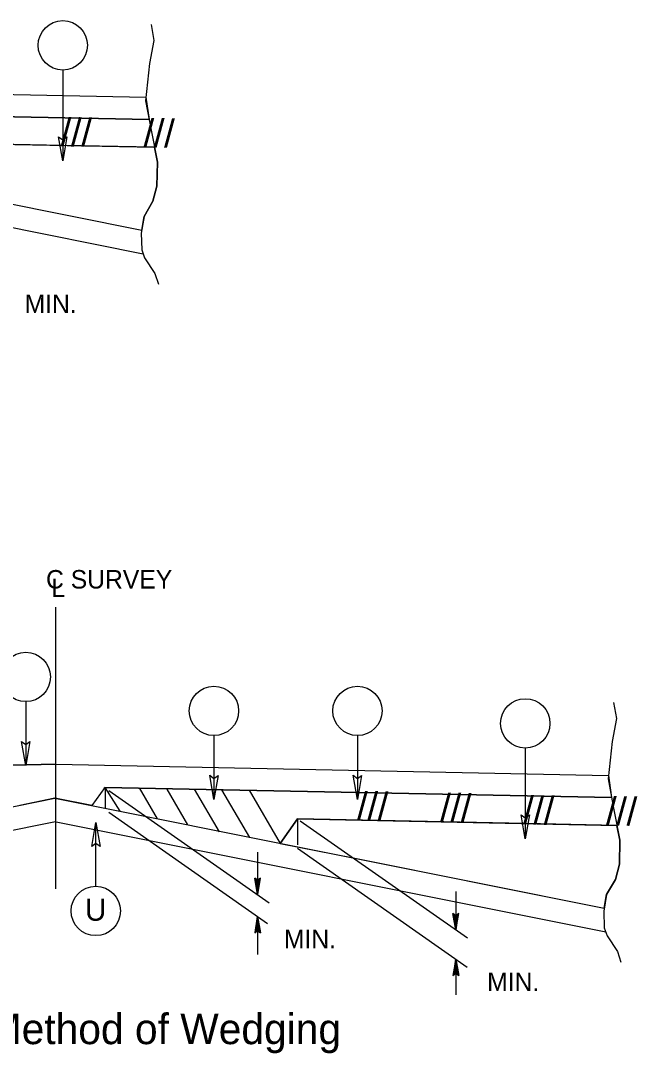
# Model space of a CAD drawing. Extents: x 1818040 to 1825768, y 638918 to 648046.
# Drawn here: x 1824618 to 1824981, y 640342 to 640948 of the extents above; entities that cross this region are included whole.
import ezdxf

# ---------------------------------------------------------------- set-up
doc = ezdxf.new("R2010")
doc.units = 0
for name, color, linetype in [('Typical Detail Wedge2 CELL', 7, 'Continuous'), ('Typical ID Circle CELL', 7, 'Continuous'), ('Typical Terminator CELL', 7, 'Continuous'), ('Typical Text Centerline CELL', 7, 'Continuous'), ('Typical Text General CELL', 7, 'Continuous'), ('Typical Text ID Circle CELL', 7, 'Continuous')]:
    doc.layers.add(name, color=color, linetype=linetype)

msp = doc.modelspace()

# ---------------------------------------------------------------- linework, layer by layer
at = {"layer": 'Typical Detail Wedge2 CELL'}
for p, q in [((1824367.22, 640909.96), (1824691.9, 640903.48)), ((1824367.25, 640909.96), (1824691.9, 640903.48)), ((1824691.9, 640903.48), (1824693.76, 640890.43)), ((1824395.95, 640896.39), (1824693.76, 640890.43)), ((1824693.76, 640890.43), (1824395.95, 640896.39)), ((1824366.74, 640890), (1824689.47, 640825.45)), ((1824509.25, 640877.84), (1824696.91, 640874.08)), ((1824643.09, 640875.16), (1824509.25, 640877.84)), ((1824367.35, 640876.11), (1824690.31, 640811.51)), ((1824696.91, 640874.08), (1824643.09, 640875.16)), ((1824541.94, 640854.95), (1824689.47, 640825.45)), ((1824638.97, 640438.55), (1824638.97, 640603.98)), ((1824638.97, 640438.55), (1824638.97, 640551.53)), ((1824638.96, 640511.63), (1824314.3, 640505.15)), ((1824314.3, 640505.15), (1824638.96, 640511.63)), ((1824638.96, 640511.63), (1824963.65, 640505.15)), ((1824639, 640511.63), (1824963.65, 640505.15)), ((1824963.65, 640505.15), (1824965.51, 640492.11)), ((1824667.69, 640498.06), (1824660.16, 640487.37)), ((1824667.69, 640498.06), (1824660.16, 640487.37)), ((1824667.21, 640497.82), (1824667.68, 640497.8)), ((1824667.69, 640498.06), (1824965.51, 640492.11)), ((1824965.51, 640492.11), (1824667.69, 640498.06)), ((1824676.69, 640484.18), (1824667.88, 640497.94)), ((1824667.88, 640497.94), (1824667.88, 640485.48)), ((1824670.17, 640496.33), (1824764.42, 640430.33)), ((1824687.91, 640497.8), (1824698.51, 640479.64)), ((1824704.2, 640496.96), (1824716.35, 640476.16)), ((1824720.36, 640497), (1824735.03, 640471.87)), ((1824736.4, 640496.69), (1824752.74, 640468.65)), ((1824752.62, 640496.35), (1824770.79, 640465.2)), ((1824639.45, 640491.68), (1824316.74, 640427.12)), ((1824638.48, 640491.68), (1824617.78, 640487.37)), ((1824638.48, 640491.68), (1824961.21, 640427.12)), ((1824660.16, 640487.37), (1824638.48, 640491.68)), ((1824670.04, 640483.5), (1824763.37, 640418.16)), ((1824638.84, 640477.78), (1824316.63, 640413.33)), ((1824639.09, 640477.78), (1824962.06, 640413.18)), ((1824780.99, 640479.51), (1824770.79, 640465.2)), ((1824770.81, 640465.2), (1824780.99, 640479.51)), ((1824780.99, 640479.51), (1824968.66, 640475.75)), ((1824780.99, 640479.51), (1824780.99, 640464.3)), ((1824914.83, 640476.83), (1824780.99, 640479.51)), ((1824782.51, 640478.45), (1824880.79, 640409.63)), ((1824968.66, 640475.75), (1824914.83, 640476.83)), ((1824770.79, 640465.2), (1824813.69, 640456.62)), ((1824757.53, 640460.11), (1824757.53, 640435.16)), ((1824780.99, 640462.31), (1824880.62, 640392.53)), ((1824813.69, 640456.62), (1824961.21, 640427.12)), ((1824757.53, 640435.16), (1824755.85, 640444.71)), ((1824757.53, 640443.47), (1824755.85, 640444.71)), ((1824757.53, 640435.16), (1824756.09, 640444.53)), ((1824756.32, 640444.35), (1824757.53, 640435.16)), ((1824757.53, 640435.16), (1824756.56, 640444.17)), ((1824756.8, 640443.99), (1824757.53, 640435.16)), ((1824757.53, 640435.16), (1824757.04, 640443.83)), ((1824757.28, 640443.65), (1824757.53, 640435.16)), ((1824757.53, 640435.16), (1824759.21, 640444.71)), ((1824759.21, 640444.71), (1824757.53, 640443.47)), ((1824758.96, 640444.53), (1824757.53, 640435.16)), ((1824757.53, 640435.16), (1824758.72, 640444.35)), ((1824758.48, 640444.17), (1824757.53, 640435.16)), ((1824757.53, 640435.16), (1824758.25, 640443.99)), ((1824758.01, 640443.83), (1824757.53, 640435.16)), ((1824757.53, 640435.16), (1824757.77, 640443.65)), ((1824757.53, 640443.47), (1824757.53, 640435.16)), ((1824874.03, 640436.93), (1824874.03, 640414.37)), ((1824757.53, 640422.25), (1824755.85, 640412.7)), ((1824756.09, 640412.89), (1824757.53, 640422.25)), ((1824757.53, 640422.25), (1824756.32, 640413.06)), ((1824756.56, 640413.25), (1824757.53, 640422.25)), ((1824757.53, 640422.25), (1824756.8, 640413.41)), ((1824757.04, 640413.58), (1824757.53, 640422.25)), ((1824757.53, 640422.25), (1824757.28, 640413.76)), ((1824757.53, 640422.25), (1824757.53, 640399.93)), ((1824757.53, 640422.25), (1824759.21, 640412.7)), ((1824757.53, 640413.94), (1824757.53, 640422.25)), ((1824757.77, 640413.76), (1824757.53, 640422.25)), ((1824757.53, 640422.25), (1824758.01, 640413.58)), ((1824758.25, 640413.41), (1824757.53, 640422.25)), ((1824757.53, 640422.25), (1824758.48, 640413.25)), ((1824758.72, 640413.06), (1824757.53, 640422.25)), ((1824757.53, 640422.25), (1824758.96, 640412.89)), ((1824874.03, 640414.37), (1824872.35, 640423.91)), ((1824874.03, 640422.68), (1824872.35, 640423.91)), ((1824874.03, 640414.37), (1824872.59, 640423.73)), ((1824872.83, 640423.56), (1824874.03, 640414.37)), ((1824874.03, 640414.37), (1824873.07, 640423.39)), ((1824873.3, 640423.2), (1824874.03, 640414.37)), ((1824874.03, 640414.37), (1824873.54, 640423.03)), ((1824873.78, 640422.84), (1824874.03, 640414.37)), ((1824874.03, 640414.37), (1824875.72, 640423.91)), ((1824875.72, 640423.91), (1824874.03, 640422.68)), ((1824875.46, 640423.73), (1824874.03, 640414.37)), ((1824874.03, 640414.37), (1824875.23, 640423.56)), ((1824874.99, 640423.39), (1824874.03, 640414.37)), ((1824874.03, 640414.37), (1824874.75, 640423.2)), ((1824874.51, 640423.03), (1824874.03, 640414.37)), ((1824874.03, 640414.37), (1824874.27, 640422.84)), ((1824874.03, 640422.68), (1824874.03, 640414.37)), ((1824755.85, 640412.7), (1824757.53, 640413.94)), ((1824757.53, 640413.94), (1824759.21, 640412.7)), ((1824874.03, 640397.16), (1824872.35, 640387.61)), ((1824872.59, 640387.79), (1824874.03, 640397.16)), ((1824874.03, 640397.16), (1824872.83, 640387.97)), ((1824873.07, 640388.15), (1824874.03, 640397.16)), ((1824874.03, 640397.16), (1824873.3, 640388.32)), ((1824873.54, 640388.5), (1824874.03, 640397.16)), ((1824874.03, 640397.16), (1824873.78, 640388.67)), ((1824874.03, 640397.16), (1824874.03, 640376.2)), ((1824874.03, 640397.16), (1824875.72, 640387.61)), ((1824874.03, 640388.86), (1824874.03, 640397.16)), ((1824874.27, 640388.67), (1824874.03, 640397.16)), ((1824874.03, 640397.16), (1824874.51, 640388.5)), ((1824874.75, 640388.32), (1824874.03, 640397.16)), ((1824874.03, 640397.16), (1824874.99, 640388.15)), ((1824875.23, 640387.97), (1824874.03, 640397.16)), ((1824874.03, 640397.16), (1824875.46, 640387.79)), ((1824872.35, 640387.61), (1824874.03, 640388.86)), ((1824874.03, 640388.86), (1824875.72, 640387.61))]:
    msp.add_line(p, q, dxfattribs=at)
for points in [[(1824694.91, 640946.33), (1824696.64, 640936.82), (1824694.05, 640923.29), (1824691.75, 640901.4), (1824694.91, 640884.12), (1824698.66, 640865.41), (1824698.37, 640851.29), (1824696.06, 640842.37), (1824690.87, 640833.43), (1824689.16, 640823.64), (1824689.43, 640813.86), (1824691.16, 640809.24), (1824697.2, 640800.02), (1824699.22, 640793.68)], [(1824689.47, 640825.45), (1824690.87, 640833.43), (1824696.06, 640842.37), (1824698.37, 640851.29), (1824698.66, 640865.41), (1824696.91, 640874.08)], [(1824966.65, 640548), (1824968.38, 640538.49), (1824965.79, 640524.96), (1824963.49, 640503.07), (1824966.65, 640485.79), (1824970.4, 640467.08), (1824970.11, 640452.96), (1824967.8, 640444.04), (1824962.62, 640435.1), (1824960.9, 640425.31), (1824961.17, 640415.53), (1824962.91, 640410.91), (1824968.94, 640401.69), (1824970.96, 640395.35)], [(1824961.21, 640427.12), (1824962.62, 640435.1), (1824967.8, 640444.04), (1824970.11, 640452.96), (1824970.4, 640467.08), (1824968.66, 640475.75)]]:
    msp.add_lwpolyline(points, dxfattribs=at)
at = {"layer": 'Typical ID Circle CELL'}
for p, q in [((1824643.09, 640919.5), (1824643.09, 640866.21)), ((1824621.34, 640548.44), (1824621.34, 640510.96)), ((1824731.88, 640528.52), (1824731.88, 640491.04)), ((1824816.23, 640528.52), (1824816.23, 640491.04)), ((1824914.83, 640521.17), (1824914.83, 640467.88)), ((1824662.46, 640439.98), (1824662.46, 640477.46))]:
    msp.add_line(p, q, dxfattribs=at)
for centre in [(1824643.08, 640934), (1824621.34, 640562.94), (1824731.88, 640543.02), (1824816.23, 640543.02), (1824914.82, 640535.67), (1824662.46, 640425.48)]:
    msp.add_circle(centre, 14.5, dxfattribs=at)
at = {"layer": 'Typical Terminator CELL'}
for points in [[(1824645.51, 640880.27), (1824643.09, 640866.21), (1824640.59, 640880.34), (1824643.09, 640878.55)], [(1824623.77, 640525.02), (1824621.34, 640510.96), (1824618.84, 640525.1), (1824621.34, 640523.31)], [(1824623.77, 640525.02), (1824621.34, 640510.96), (1824618.84, 640525.1), (1824621.34, 640523.31)], [(1824734.3, 640505.1), (1824731.88, 640491.04), (1824729.38, 640505.18), (1824731.88, 640503.38)], [(1824734.3, 640505.1), (1824731.88, 640491.04), (1824729.38, 640505.18), (1824731.88, 640503.38)], [(1824818.65, 640505.1), (1824816.23, 640491.04), (1824813.73, 640505.18), (1824816.23, 640503.38)], [(1824818.65, 640505.1), (1824816.23, 640491.04), (1824813.73, 640505.18), (1824816.23, 640503.38)], [(1824660.04, 640463.4), (1824662.46, 640477.46), (1824664.96, 640463.32), (1824662.46, 640465.12)], [(1824660.04, 640463.4), (1824662.46, 640477.46), (1824664.96, 640463.32), (1824662.46, 640465.12)], [(1824917.25, 640481.94), (1824914.83, 640467.88), (1824912.33, 640482.01), (1824914.83, 640480.22)]]:
    msp.add_lwpolyline(points, close=True, dxfattribs=at)

# ---------------------------------------------------------------- texts
at = {"layer": 'Typical Detail Wedge2 CELL'}
for height, rotation, p in [(16.281, 358.85537, (1824641.78, 640874.88)), (16.281, 358.85371, (1824690.45, 640874.31)), (16.276, 358.85527, (1824815.95, 640478.99)), (16.275, 358.85361, (1824864.77, 640477.99)), (16.281, 358.85537, (1824913.53, 640476.55)), (16.281, 358.85371, (1824962.19, 640475.98))]:
    msp.add_text('/// ', height=height, rotation=rotation, dxfattribs=at).set_placement(p)
for p in [(1824620.66, 640776.76), (1824773.02, 640403.58), (1824892.4, 640378.43)]:
    msp.add_text('MIN.', height=10.846, dxfattribs=at).set_placement(p)
at = {"layer": 'Typical Text Centerline CELL'}
for s, height, p in [('C SURVEY ', 10.846, (1824633.23, 640614.9)), ('L', 10.85, (1824636.41, 640609.83))]:
    msp.add_text(s, height=height, dxfattribs=at).set_placement(p)
at = {"layer": 'Typical Text General CELL'}
msp.add_text('Detail Showing Method of Wedging', height=17.9034, dxfattribs=at).set_placement((1824432.62, 640347.23))
at = {"layer": 'Typical Text ID Circle CELL'}
msp.add_text('U', height=12.98, dxfattribs=at).set_placement((1824656.12, 640419.74))

doc.saveas('drawing.dxf')
